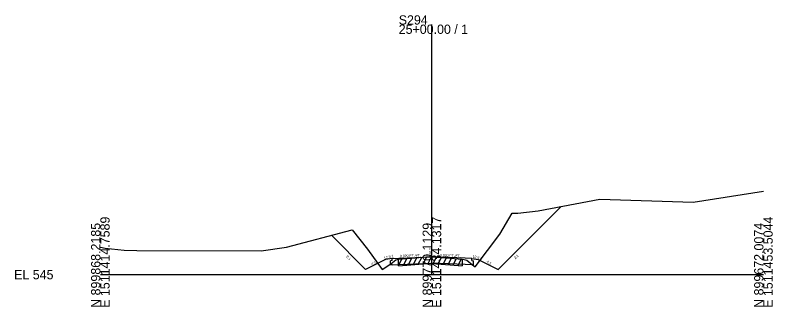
# Model space of a CAD drawing. Extents: x 974 to 2203, y -10 to 19041.
# Drawn here: x 1974.3 to 2202.8, y 9990.3 to 10078.2 of the extents above; entities that cross this region are included whole.
import ezdxf

# ---------------------------------------------------------------- set-up
doc = ezdxf.new("R2010")
doc.units = 0
for name, color, linetype in [('RD_GPK_XS_Cell', 7, 'Continuous'), ('RD_XS_Base', 7, 'Continuous'), ('RD_XS_EarthShd', 7, 'Continuous'), ('RD_XS_ExGround', 7, 'Continuous'), ('RD_XS_ExPaveRet', 7, 'Continuous'), ('RD_XS_Pave', 7, 'Continuous'), ('RD_XS_TX_Elev_EX', 7, 'Continuous'), ('RD_XS_TX_Slope', 7, 'Continuous')]:
    doc.layers.add(name, color=color, linetype=linetype)

msp = doc.modelspace()

# ---------------------------------------------------------------- linework, layer by layer
at = {"layer": 'RD_GPK_XS_Cell'}
for p, q in [((2100, 10000), (2100, 10075.35)), ((2000, 10000), (2100, 10000)), ((2100, 10000), (2200, 10000))]:
    msp.add_line(p, q, dxfattribs=at)
at = {"layer": 'RD_XS_Base'}
for p, q in [((2088, 10004.23), (2087.48, 10004.21)), ((2087.48, 10002.94), (2087.48, 10004.21)), ((2087.98, 10002.96), (2087.48, 10002.94)), ((2087.98, 10002.96), (2090, 10003.04)), ((2088, 10004.23), (2088, 10004.87)), ((2090, 10003.04), (2100, 10003.44)), ((2110, 10003.04), (2100, 10003.44)), ((2112.02, 10002.96), (2110, 10003.04)), ((2112, 10004.23), (2112, 10004.87)), ((2112, 10004.23), (2112.52, 10004.21)), ((2112.02, 10002.96), (2112.52, 10002.94)), ((2112.52, 10002.94), (2112.52, 10004.21))]:
    msp.add_line(p, q, dxfattribs=at)
at = {"layer": 'RD_XS_EarthShd'}
for p, q in [((2120, 10001.54), (2139.02, 10020.55)), ((2080, 10001.54), (2069.68, 10011.86)), ((2086, 10004.54), (2080, 10001.54)), ((2088, 10004.87), (2086, 10004.54)), ((2112, 10004.87), (2114, 10004.54)), ((2114, 10004.54), (2120, 10001.54))]:
    msp.add_line(p, q, dxfattribs=at)
at = {"layer": 'RD_XS_ExGround'}
msp.add_lwpolyline([(2000, 10008.27), (2001.49, 10007.96), (2007.2, 10007.35), (2010.98, 10007.23), (2048.47, 10007.18), (2056.11, 10008.29), (2075.99, 10013.52), (2080.62, 10007.73), (2085.05, 10001.54), (2087.61, 10003.3), (2089.11, 10004.45), (2089.55, 10004.61), (2089.89, 10004.67), (2093.69, 10004.93), (2099.55, 10005.45), (2100, 10005.41), (2105.52, 10004.92), (2109.12, 10004.68), (2109.71, 10004.55), (2110.54, 10004.41), (2112.24, 10002.95), (2113.05, 10002.35), (2120.47, 10012.25), (2124.23, 10018.52), (2125.96, 10018.51), (2132.02, 10019.21), (2150.68, 10022.79), (2178.83, 10021.84), (2200, 10025.12)], dxfattribs=at)
at = {"layer": 'RD_XS_ExPaveRet'}
for p, q in [((2095.89, 10003.13), (2096.94, 10005.22)), ((2097.39, 10003.26), (2098.44, 10005.36)), ((2098.89, 10003.4), (2099.91, 10005.42)), ((2100.39, 10003.38), (2101.35, 10005.29)), ((2101.89, 10003.24), (2102.85, 10005.16)), ((2089.89, 10002.67), (2090.93, 10004.74)), ((2089.89, 10002.67), (2089.89, 10004.67)), ((2089.89, 10002.67), (2093.69, 10002.93)), ((2091.39, 10002.78), (2092.43, 10004.85)), ((2092.89, 10002.88), (2093.93, 10004.95)), ((2093.69, 10002.93), (2099.55, 10003.45)), ((2094.39, 10003), (2095.44, 10005.09)), ((2099.55, 10003.45), (2100, 10003.41)), ((2100, 10003.41), (2105.52, 10002.92)), ((2103.39, 10003.11), (2104.35, 10005.02)), ((2104.89, 10002.98), (2105.86, 10004.9)), ((2105.52, 10002.92), (2109.12, 10002.68)), ((2106.39, 10002.86), (2107.36, 10004.8)), ((2107.89, 10002.76), (2108.86, 10004.7)), ((2109.12, 10004.68), (2109.12, 10002.68))]:
    msp.add_line(p, q, dxfattribs=at)
at = {"layer": 'RD_XS_Pave'}
for p, q in [((2090, 10004.95), (2100, 10005.35)), ((2110, 10004.95), (2100, 10005.35)), ((2088, 10004.87), (2090, 10004.95)), ((2112, 10004.87), (2110, 10004.95))]:
    msp.add_line(p, q, dxfattribs=at)

# ---------------------------------------------------------------- texts
at = {"layer": 'RD_GPK_XS_Cell'}
for s, p in [('S294', (2090, 10075.35)), ('25+00.00 / 1', (2090, 10072.55)), ('EL 545', (1974, 9998.6))]:
    msp.add_text(s, height=2.8, dxfattribs=at).set_placement(p)
for s, p in [('E 1511414.7589', (2002.8, 9990)), ('E 1511434.1317', (2102.8, 9990)), ('E 1511453.5044', (2202.8, 9990)), ('N 899868.2185', (2000, 9990)), ('N 899770.1129', (2100, 9990)), ('N 899672.0074', (2200, 9990))]:
    msp.add_text(s, height=2.8, rotation=90, dxfattribs=at).set_placement(p)
at = {"layer": 'RD_XS_TX_Elev_EX'}
msp.add_text('547.71', height=0.75, rotation=90, dxfattribs=at).set_placement((2100, 10005.41))
at = {"layer": 'RD_XS_TX_Slope'}
for s, height, rotation, p in [('2:1', 0.778, 319.3411, (2074.04, 10005.32)), ('12.5:1', 0.778, 12.7511, (2085.61, 10004.61)), ('0.020 FT./FT.', 0.7518, 2.396, (2090.38, 10005.21)), ('0.020 FT./FT.', 0.7518, 357.604, (2102.4, 10005.51)), ('12.5:1', 0.778, 347.2489, (2112.17, 10005.12)), ('2:1', 0.778, 40.6589, (2125.1, 10004.59)), ('4:1', 0.778, 26.3688, (2081.93, 10002.79)), ('4:1', 0.778, 333.6312, (2116.43, 10003.65))]:
    msp.add_text(s, height=height, rotation=rotation, dxfattribs=at).set_placement(p)

doc.saveas('drawing.dxf')
